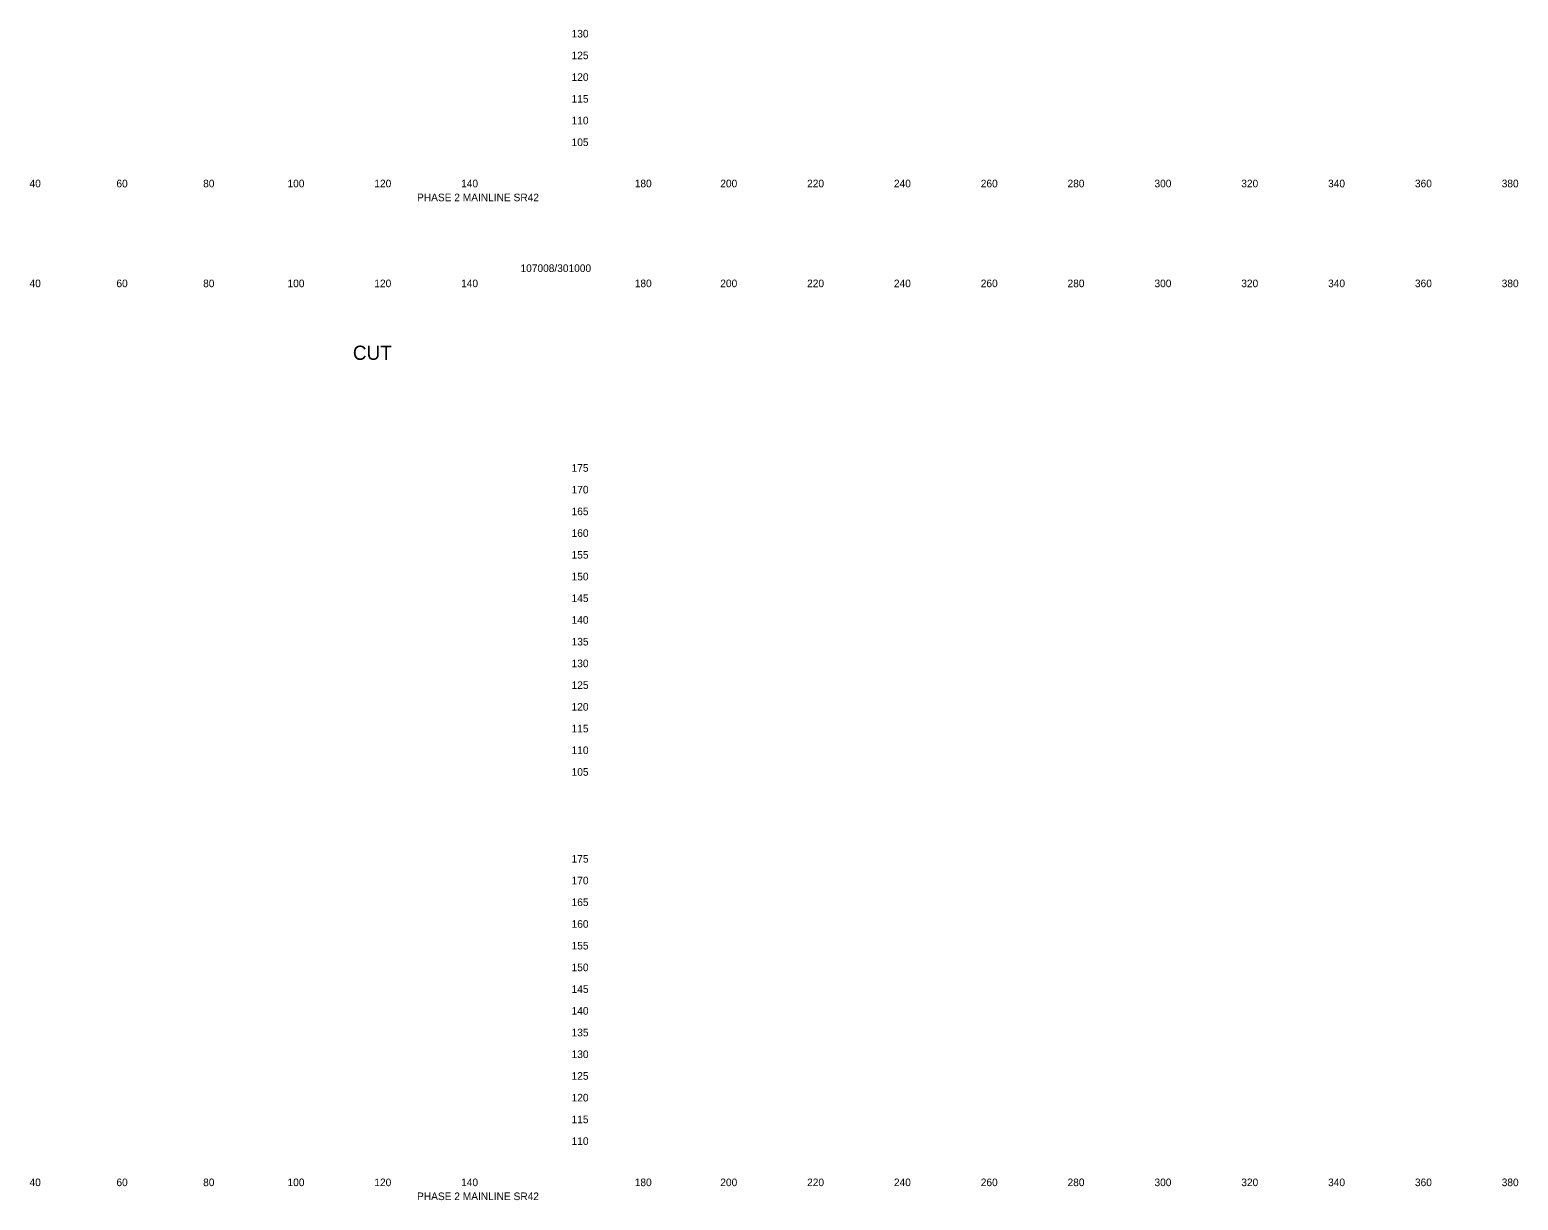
# Model space of a CAD drawing. Extents: x 21281 to 22024, y 6472 to 15208.
# Drawn here: x 21681.3 to 22024.2, y 10842.1 to 11111.6 of the extents above; entities that cross this region are included whole.
import ezdxf

# ---------------------------------------------------------------- set-up
doc = ezdxf.new("R2010")
doc.units = 0
doc.layers.add('XS_SHEET_LABELS_ELEVATION', color=7, linetype='Continuous')
doc.layers.add('XS_SHEET_LABELS_OFFSET', color=7, linetype='Continuous')

msp = doc.modelspace()

# ---------------------------------------------------------------- texts
at = {"layer": 'XS_SHEET_LABELS_ELEVATION'}
for s, p in [('  130  ', (21804.84, 11109.84)), ('  125  ', (21804.84, 11104.84)), ('  120  ', (21804.84, 11099.84)), ('  115  ', (21804.84, 11094.84)), ('  110  ', (21804.84, 11089.84)), ('  105  ', (21804.84, 11084.84)), ('  175  ', (21804.84, 11009.84)), ('  170  ', (21804.84, 11004.84)), ('  165  ', (21804.84, 10999.84)), ('  160  ', (21804.84, 10994.84)), ('  155  ', (21804.84, 10989.84)), ('  150  ', (21804.84, 10984.84)), ('  145  ', (21804.84, 10979.84)), ('  140  ', (21804.84, 10974.84)), ('  135  ', (21804.84, 10969.84)), ('  130  ', (21804.84, 10964.84)), ('  125  ', (21804.84, 10959.84)), ('  120  ', (21804.84, 10954.84)), ('  115  ', (21804.84, 10949.84)), ('  110  ', (21804.84, 10944.84)), ('  105  ', (21804.84, 10939.84)), ('  175  ', (21804.84, 10919.84)), ('  170  ', (21804.84, 10914.84)), ('  165  ', (21804.84, 10909.84)), ('  160  ', (21804.84, 10904.84)), ('  155  ', (21804.84, 10899.84)), ('  150  ', (21804.84, 10894.84)), ('  145  ', (21804.84, 10889.84)), ('  140  ', (21804.84, 10884.84)), ('  135  ', (21804.84, 10879.84)), ('  130  ', (21804.84, 10874.84)), ('  125  ', (21804.84, 10869.84)), ('  120  ', (21804.84, 10864.84)), ('  115  ', (21804.84, 10859.84)), ('  110  ', (21804.84, 10854.84))]:
    msp.add_text(s, height=1.75, dxfattribs=at).set_placement(p)
at = {"layer": 'XS_SHEET_LABELS_OFFSET'}
for s, height, p in [('  40  ', 1.75, (21679.95, 11075.34)), ('  60  ', 1.75, (21699.97, 11075.34)), ('  80  ', 1.75, (21719.95, 11075.34)), ('  100  ', 1.75, (21739.39, 11075.34)), ('  120  ', 1.75, (21759.39, 11075.34)), ('  140  ', 1.75, (21779.39, 11075.34)), ('  180  ', 1.75, (21819.39, 11075.34)), ('  200  ', 1.75, (21839.1, 11075.34)), ('  220  ', 1.75, (21859.1, 11075.34)), ('  240  ', 1.75, (21879.1, 11075.34)), ('  260  ', 1.75, (21899.11, 11075.34)), ('  280  ', 1.75, (21919.1, 11075.34)), ('  300  ', 1.75, (21939.13, 11075.34)), ('  320  ', 1.75, (21959.13, 11075.34)), ('  340  ', 1.75, (21979.13, 11075.34)), ('  360  ', 1.75, (21999.14, 11075.34)), ('  380  ', 1.75, (22019.13, 11075.34)), ('PHASE 2 MAINLINE SR42', 1.75, (21770.53, 11072.13)), ('107008/301000', 1.75, (21794.37, 11055.84)), ('  40  ', 1.75, (21679.95, 11052.34)), ('  60  ', 1.75, (21699.97, 11052.34)), ('  80  ', 1.75, (21719.95, 11052.34)), ('  100  ', 1.75, (21739.39, 11052.34)), ('  120  ', 1.75, (21759.39, 11052.34)), ('  140  ', 1.75, (21779.39, 11052.34)), ('  180  ', 1.75, (21819.39, 11052.34)), ('  200  ', 1.75, (21839.1, 11052.34)), ('  220  ', 1.75, (21859.1, 11052.34)), ('  240  ', 1.75, (21879.1, 11052.34)), ('  260  ', 1.75, (21899.11, 11052.34)), ('  280  ', 1.75, (21919.1, 11052.34)), ('  300  ', 1.75, (21939.13, 11052.34)), ('  320  ', 1.75, (21959.13, 11052.34)), ('  340  ', 1.75, (21979.13, 11052.34)), ('  360  ', 1.75, (21999.14, 11052.34)), ('  380  ', 1.75, (22019.13, 11052.34)), ('CUT', 3.273, (21755.74, 11035.61)), ('  40  ', 1.75, (21679.95, 10845.34)), ('  60  ', 1.75, (21699.97, 10845.34)), ('  80  ', 1.75, (21719.95, 10845.34)), ('  100  ', 1.75, (21739.39, 10845.34)), ('  120  ', 1.75, (21759.39, 10845.34)), ('  140  ', 1.75, (21779.39, 10845.34)), ('  180  ', 1.75, (21819.39, 10845.34)), ('  200  ', 1.75, (21839.1, 10845.34)), ('  220  ', 1.75, (21859.1, 10845.34)), ('  240  ', 1.75, (21879.1, 10845.34)), ('  260  ', 1.75, (21899.11, 10845.34)), ('  280  ', 1.75, (21919.1, 10845.34)), ('  300  ', 1.75, (21939.13, 10845.34)), ('  320  ', 1.75, (21959.13, 10845.34)), ('  340  ', 1.75, (21979.13, 10845.34)), ('  360  ', 1.75, (21999.14, 10845.34)), ('  380  ', 1.75, (22019.13, 10845.34)), ('PHASE 2 MAINLINE SR42', 1.75, (21770.53, 10842.13))]:
    msp.add_text(s, height=height, dxfattribs=at).set_placement(p)

doc.saveas('drawing.dxf')
